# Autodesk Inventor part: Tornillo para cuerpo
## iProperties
Shininess: 64.0
Length Units: 11272
Angle Units: 11279
Time Units: 11290
Mass Units: 11286
Length Display Precision: 3
Angle Display Precision: 2
Compacted: True
Part Number: Tornillo para cuerpo
Document SubType Name: Modeling
Created: 2005-06
Designer: alek
Manufacturer: Standard
Standards Organization: Custom
Density: 0.0
Volumn: 0.0
Area: 0.0
PropertySet Name: Model Information
Control State: 0
Master: False
Checked Out: False
Author: alek
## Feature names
1. Revolution1
2. Extrusion1
